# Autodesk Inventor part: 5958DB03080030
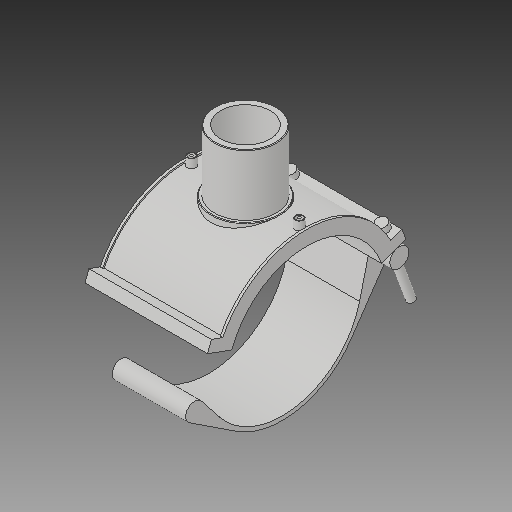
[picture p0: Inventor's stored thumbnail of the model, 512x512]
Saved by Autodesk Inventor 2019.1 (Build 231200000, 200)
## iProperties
Created: 2017-07
Part Number: 5958DB03080030
Material: Generic
Description: PLASSON BRANCH SADDLE 8''DIPS x 3''IPS
Document SubType Name: Modeling
Designer: KIM
Mass: 764.267 g
Surface Area: 1930.38 cm^2
Volume: 764.267 cm^3
Density: 1 g/cm^3
Appearance: Default
Author: KIM
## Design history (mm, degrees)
derived "5958D (2).ipt"
feature "Solid6::5958D (2).ipt"
tag "TaggingFeature1"
body "Solid1"
other parameters: "d_" = 228.9, "d1" = 88.7, "B_" = 179.832, "H_" = 106.934, "H1" = 88.392, "L" = 176.022, "t" = 6, "d244" = 228.9, "d245" = 18.542, "d248" = 179.832, "d249" = 89.916, "d252" = 114.45, "d254" = 18.542, "d256" = 539.496, "d257" = 28.6125, "d258" = 269.748, "d259" = 0.5, "d260" = 176.022, "d261" = 0, "d287" = 133.73368, "d288" = 97.57, "d290" = 0, "d291" = 221.384, "d292" = 88.7, "d294" = 0, "d309" = 144.45, "d310" = 12, "d311" = 12, "d315" = 3 deg, "d316" = 4, "d318" = 4, "d320" = 14, "d321" = 0, "d331" = 0.887, "d332" = 70.96, "d334" = 0, "d337" = 0.887, "d340" = 10.56132, "d341" = 10.56132, "d342" = 20 deg, "d343" = 20 deg, "d344" = 719.328, "d345" = 228.9, "d347" = 0, "d352" = 37.084, "d353" = 16.023, "d355" = 0, "d356" = 20 deg, "d357" = 34.335, "d358" = 228.9, "d359" = 240.345, "d360" = 27.468, "d361" = 10 deg, "d362" = 8.25119, "d363" = 45.78, "d366" = 125.895, "d367" = 8.62203, "d368" = 105.6132, "d369" = 0, "d370" = 158.4198, "d371" = 0, "d372" = 132.0165, "d374" = 11.445, "d375" = 16.023, "d376" = 11.445, "d377" = 16.023, "d378" = 114.45, "d379" = 0, "d380" = 9.6138, "d381" = 0, "d383" = 142.263, "d384" = 17.6022, "d385" = 2.289, "d386" = 3.52044, "d387" = 0, "d389" = 360 deg
